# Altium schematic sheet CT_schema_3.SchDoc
size 259 x 245 mm
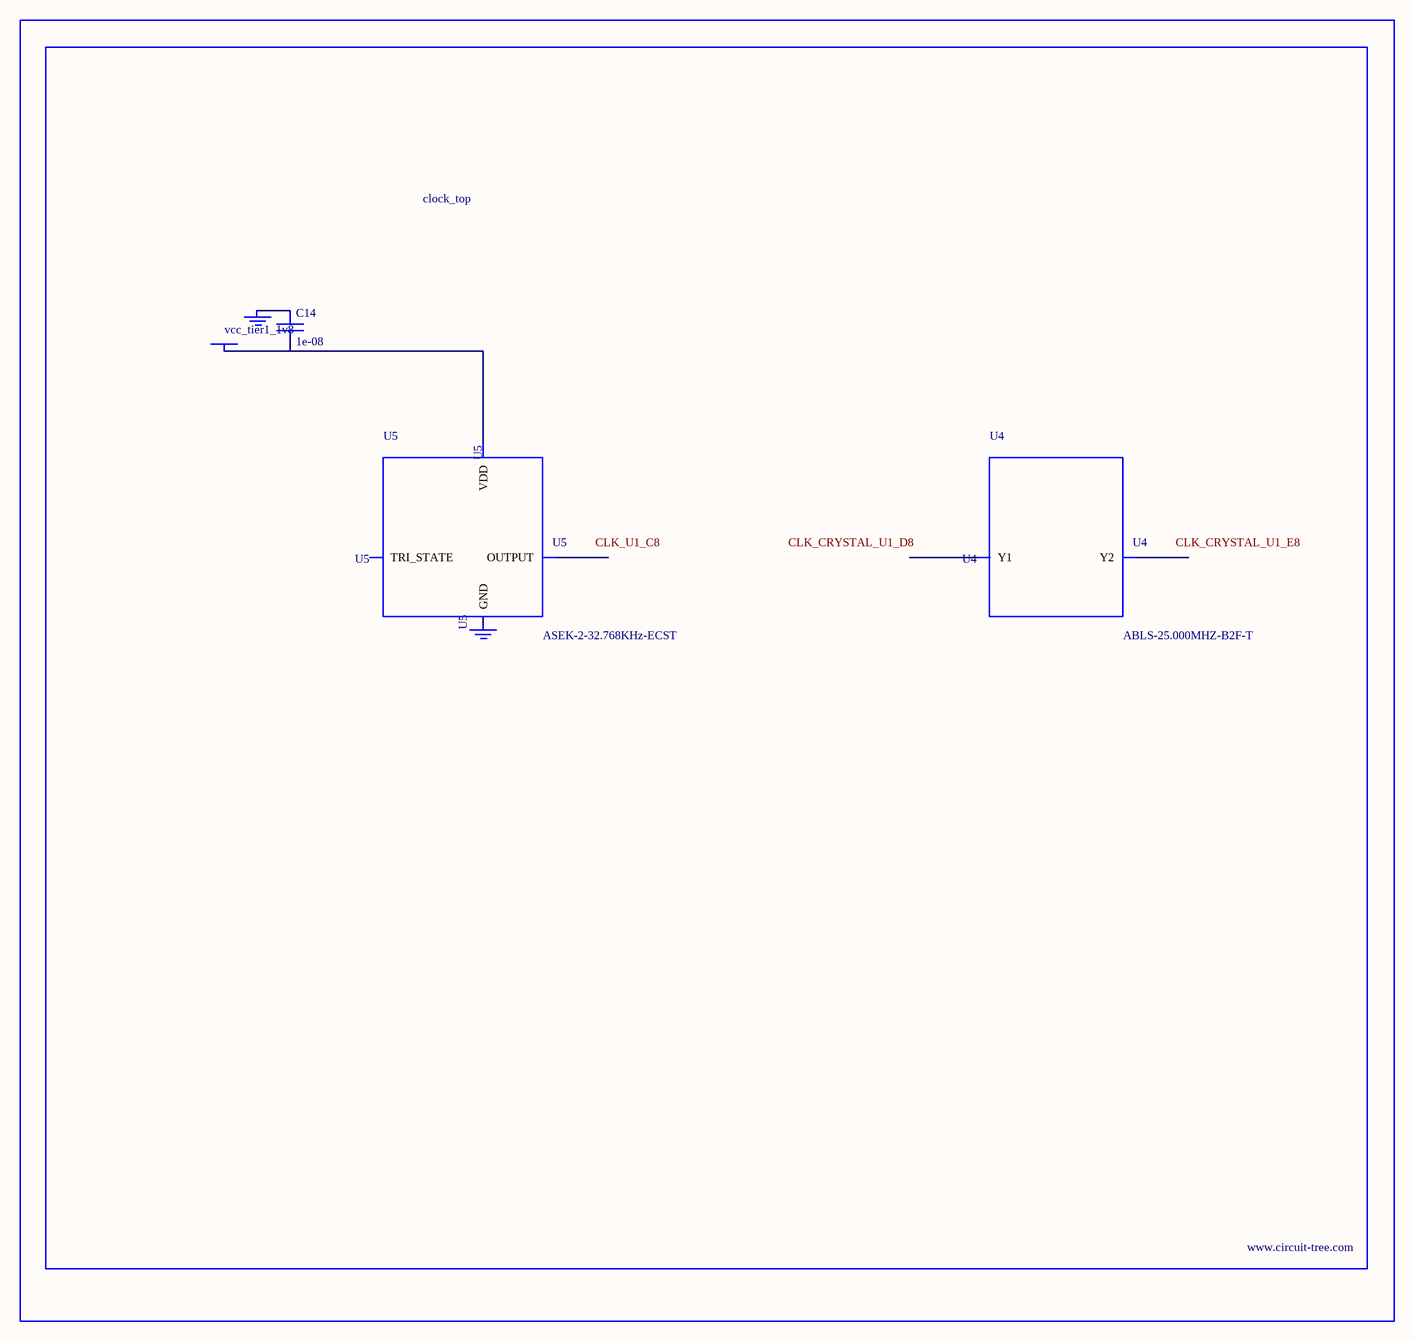
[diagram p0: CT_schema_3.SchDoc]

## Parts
BORDER2  (no value)
C14  1e-08  [C0402]
GND_INSTANCE_2_0  (no value)
GND_INSTANCE_2_1  (no value)
POWER_INSTANCE_2_0  vcc_tier1_1v8
U4  ABLS-25.000MHZ-B2F-T  [ABLS-25.000MHZ-B2F-T]
U5  ASEK-2-32.768KHz-ECST  [ASEK]

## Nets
NetC14_1: C14.1 GND_INSTANCE_2_0.0(GND)
NetC14_2: C14.2 POWER_INSTANCE_2_0.0(PWR) U5.4(VDD)

Not connected (* = marked no-connect by the designer): GND_INSTANCE_2_1 0(GND); U4 1(Y1) 2(Y2); U5 1(TRI_STATE) 2(GND) 3(OUTPUT)

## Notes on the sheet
- Labels drawn without touching a wire or pin: CLK_CRYSTAL_U1_D8, CLK_CRYSTAL_U1_E8, CLK_U1_C8

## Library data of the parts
BORDER2 = BORDER_PAGE2
C14 = C0402C103K3RAC
GND_INSTANCE_2_0 GND_INSTANCE_2_1 = GND
POWER_INSTANCE_2_0 = PWR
